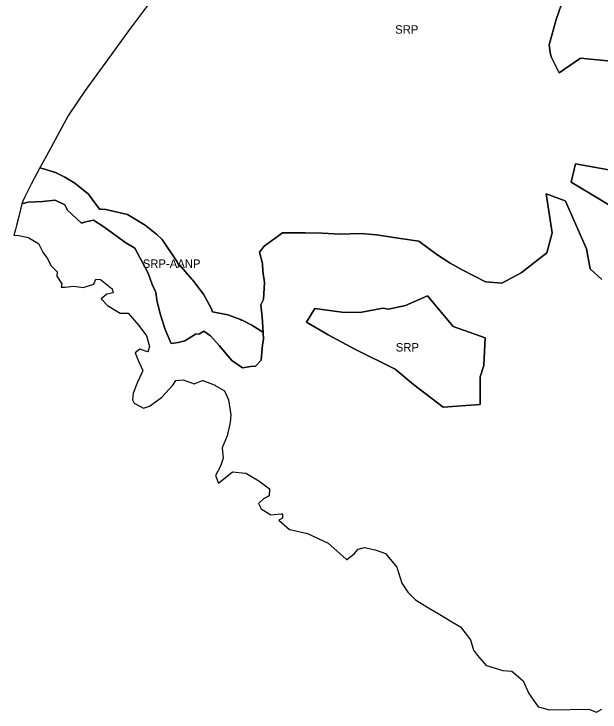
# Model space of a CAD drawing. Extents: x 598968 to 613553, y 4409678 to 4430833.
# Drawn here: x 598968 to 599801, y 4411640 to 4412632 of the extents above; entities that cross this region are included whole.
import ezdxf

# ---------------------------------------------------------------- set-up
doc = ezdxf.new("R2010")
doc.units = 0
doc.layers.add('Sòl Rústic Protegit', color=7, linetype='Continuous')
doc.layers.add('Sòl Rústic Protegit - Alt Nivell de Protecció', color=7, linetype='Continuous')

msp = doc.modelspace()

# ---------------------------------------------------------------- linework, layer by layer
at = {"layer": 'Sòl Rústic Protegit'}
for points in [[(599167.4801, 4412657.9802), (599130.5701, 4412607.8402), (599101.9801, 4412568.9202), (599068.9101, 4412523.2802), (599045.2201, 4412487.9502), (599014.1301, 4412430.5402), (599004.6743, 4412413.1288), (599009.8671, 4412412.0102), (599027.0547, 4412406.5102), (599040.1797, 4412400.0102), (599054.3671, 4412391.5102), (599073.6797, 4412376.0102), (599089.2423, 4412354.5102), (599091.6171, 4412354.5102), (599098.3671, 4412354.0102), (599129.2423, 4412347.0102), (599154.3047, 4412332.0102), (599170.8047, 4412318.5102), (599178.1797, 4412311.5102), (599199.8671, 4412279.5102), (599200.4923, 4412277.5102), (599200.9297, 4412277.0102), (599202.9297, 4412274.0102), (599205.3671, 4412272.5102), (599220.7421, 4412255.0102), (599221.8047, 4412253.5102), (599226.4297, 4412248.0102), (599236.9923, 4412233.5102), (599248.5547, 4412213.0102), (599250.1173, 4412208.5102), (599271.8047, 4412204.5102), (599289.9297, 4412197.5102), (599290.9297, 4412196.5102), (599292.1797, 4412196.5102), (599305.6173, 4412189.5102), (599318.8671, 4412181.5102), (599321.9925, 4412179.01), (599320.6801, 4412201.5098), (599318.8051, 4412218.5098), (599322.3677, 4412226.0098), (599323.9927, 4412250.5098), (599321.4927, 4412266.5098), (599321.0551, 4412277.5098), (599316.6177, 4412293.5098), (599323.3677, 4412302.0098), (599349.4927, 4412321.0098), (599381.4301, 4412321.0098), (599405.7427, 4412320.5098), (599431.4301, 4412319.0098), (599445.4301, 4412319.5098), (599460.7427, 4412320.0098), (599483.1801, 4412318.0098), (599517.3051, 4412313.0098), (599542.9927, 4412309.0098), (599568.6177, 4412290.0098), (599587.6177, 4412278.0098), (599604.6177, 4412268.5098), (599637.8677, 4412251.0098), (599660.9301, 4412249.5098), (599688.5551, 4412264.0098), (599725.1801, 4412292.5098), (599732.4301, 4412321.0098), (599723.9301, 4412376.5098), (599751.1801, 4412366.5098), (599751.3801, 4412366.0538), (599781.2427, 4412298.0098), (599786.7427, 4412269.5098), (599803.3051, 4412254.5098)], [(599815.9927, 4412565.0098), (599772.8879, 4412569.1888), (599742.8283, 4412548.3784), (599731.3677, 4412571.0098), (599729.8677, 4412577.5098), (599728.1801, 4412588.0098), (599738.3677, 4412624.0098), (599749.3051, 4412656.0098)], [(599848.5769, 4412339.5676), (599759.4317, 4412392.7276), (599765.9745, 4412418.8986), (599828.9485, 4412407.4488)]]:
    msp.add_lwpolyline(points, dxfattribs=at)
msp.add_lwpolyline([(599555.4927, 4412231.5098), (599524.0551, 4412217.5098), (599499.9301, 4412212.5098), (599492.2427, 4412214.0098), (599459.8677, 4412207.5098), (599433.6177, 4412208.0098), (599395.2163, 4412213.0984), (599383.6549, 4412193.8296), (599414.4855, 4412176.102), (599452.2525, 4412155.2916), (599509.4927, 4412127.0098), (599535.4943, 4412105.1922), (599577.8861, 4412072.8204), (599630.2975, 4412076.6742), (599630.2975, 4412115.983), (599635.6929, 4412132.1688), (599637.2345, 4412171.4776), (599591.7597, 4412187.6634)], close=True, dxfattribs=at)
at = {"layer": 'Sòl Rústic Protegit - Alt Nivell de Protecció'}
for points in [[(599749.3051, 4412656.0098), (599738.3677, 4412624.0098), (599728.1801, 4412588.0098), (599729.8677, 4412577.5098), (599731.3677, 4412571.0098), (599742.8283, 4412548.3784), (599772.8879, 4412569.1888), (599815.9927, 4412565.0098)], [(599828.9485, 4412407.4488), (599765.9745, 4412418.8986), (599759.4317, 4412392.7276), (599848.5769, 4412339.5676)], [(599803.3051, 4412254.5098), (599786.7427, 4412269.5098), (599781.2427, 4412298.0098), (599751.3801, 4412366.0538), (599751.1801, 4412366.5098), (599723.9301, 4412376.5098), (599732.4301, 4412321.0098), (599725.1801, 4412292.5098), (599688.5551, 4412264.0098), (599660.9301, 4412249.5098), (599637.8677, 4412251.0098), (599604.6177, 4412268.5098), (599587.6177, 4412278.0098), (599568.6177, 4412290.0098), (599542.9927, 4412309.0098), (599517.3051, 4412313.0098), (599483.1801, 4412318.0098), (599460.7427, 4412320.0098), (599445.4301, 4412319.5098), (599431.4301, 4412319.0098), (599405.7427, 4412320.5098), (599381.4301, 4412321.0098), (599349.4927, 4412321.0098), (599323.3677, 4412302.0098), (599316.6177, 4412293.5098), (599321.0551, 4412277.5098), (599321.4927, 4412266.5098), (599323.9927, 4412250.5098), (599322.3677, 4412226.0098), (599318.8051, 4412218.5098), (599320.6801, 4412201.5098), (599321.9925, 4412179.01), (599322.5549, 4412169.51), (599320.9299, 4412161.51), (599319.1799, 4412140.01), (599311.1799, 4412131.51), (599304.1799, 4412131.01), (599292.7425, 4412129.01), (599277.6175, 4412139.51), (599259.6175, 4412160.51), (599246.9299, 4412174.51), (599237.7425, 4412181.01), (599231.4925, 4412177.51), (599225.7425, 4412177.01), (599216.9925, 4412171.01), (599210.7425, 4412167.51), (599201.2425, 4412165.01), (599191.0549, 4412163.51), (599182.6799, 4412183.51), (599175.4299, 4412205.51), (599170.8675, 4412225.01), (599169.1799, 4412236.51), (599168.3553, 4412238.3708), (599164.3049, 4412247.51), (599160.7425, 4412257.01), (599157.9299, 4412264.51), (599139.3675, 4412299.01), (599126.9299, 4412306.51), (599107.8675, 4412320.51), (599095.3675, 4412329.51), (599080.9925, 4412339.01), (599069.5549, 4412336.51), (599063.8675, 4412334.51), (599043.9925, 4412353.01), (599039.8675, 4412360.51), (599026.1799, 4412367.51), (599008.9925, 4412365.51), (598987.9925, 4412364.51), (598979.1175, 4412362.01), (598974.6154, 4412344.0764), (598971.3708, 4412331.1519), (598969.9525, 4412325.5023), (598967.7959, 4412316.9118), (598972.3403, 4412317.6168), (598988.5903, 4412314.1168), (598988.7487, 4412314.022), (599002.7777, 4412305.617), (599008.5903, 4412293.6172), (599016.1527, 4412283.6172), (599020.0277, 4412274.6174), (599028.9651, 4412265.6176), (599028.6527, 4412259.1176), (599035.7151, 4412248.6178), (599035.0275, 4412243.6178), (599035.2561, 4412243.6178), (599040.6525, 4412243.6178), (599052.9027, 4412245.1178), (599066.3401, 4412243.118), (599081.3401, 4412248.118), (599084.0277, 4412255.118), (599090.7777, 4412254.618), (599090.9017, 4412254.5166), (599107.2777, 4412241.1184), (599108.8401, 4412235.6184), (599099.8401, 4412233.6184), (599091.6527, 4412227.1182), (599100.5901, 4412217.6184), (599118.7777, 4412206.6186), (599118.8127, 4412206.6186), (599130.0277, 4412206.6188), (599130.1235, 4412206.5098), (599145.4025, 4412189.119), (599155.9651, 4412174.6192), (599160.5275, 4412159.1194), (599158.4151, 4412153.3584), (599157.7775, 4412151.6194), (599156.2977, 4412152.1486), (599149.3641, 4412154.6274), (599147.3355, 4412155.3526), (599146.5899, 4412155.6192), (599140.0899, 4412150.1192), (599144.5899, 4412138.6194), (599150.3277, 4412126.226), (599150.8399, 4412125.1194), (599149.8729, 4412122.9922), (599143.3397, 4412108.6196), (599137.2771, 4412093.1196), (599136.2771, 4412083.6196), (599138.7771, 4412078.6198), (599151.9021, 4412071.6198), (599151.9077, 4412071.6218), (599160.4021, 4412074.62), (599177.4023, 4412086.62), (599193.5273, 4412104.12), (599198.0273, 4412111.12), (599208.1525, 4412112.12), (599223.7149, 4412106.1202), (599235.5899, 4412111.1202), (599236.3215, 4412110.8378), (599252.3571, 4412104.6448), (599253.7149, 4412104.1204), (599253.8335, 4412104.0488), (599266.9649, 4412096.1206), (599272.7149, 4412083.6208), (599275.9023, 4412062.121), (599275.1523, 4412051.121), (599270.8397, 4412032.121), (599263.5897, 4412015.1212), (599265.2771, 4412000.6212), (599261.3395, 4411989.1214), (599254.3395, 4411976.1214), (599258.2769, 4411965.1214), (599258.4135, 4411965.2306), (599278.2771, 4411981.1216), (599296.9645, 4411979.1216), (599297.1481, 4411979.0132), (599315.5895, 4411968.1218), (599331.0271, 4411957.122), (599330.5895, 4411947.1222), (599322.2145, 4411942.6222), (599315.2145, 4411936.1222), (599319.1519, 4411928.6222), (599332.6519, 4411920.1224), (599332.6841, 4411920.1254), (599337.4215, 4411920.5496), (599347.4619, 4411921.4488), (599349.4019, 4411921.6224), (599349.4441, 4411920.163), (599349.5895, 4411915.1226), (599344.3393, 4411912.6226), (599359.5269, 4411899.1228), (599359.6441, 4411899.0974), (599384.7769, 4411893.623), (599414.3395, 4411879.6234), (599414.3669, 4411879.599), (599435.1519, 4411861.1236), (599440.5893, 4411856.6236), (599440.6305, 4411856.6544), (599451.2769, 4411864.6236), (599457.1519, 4411871.1236), (599465.8395, 4411873.6238), (599481.2769, 4411870.1238), (599495.9019, 4411865.124), (599495.9483, 4411865.0676), (599511.9645, 4411845.6244), (599519.0893, 4411822.6246), (599527.7769, 4411810.1246), (599538.5893, 4411799.1248), (599554.5267, 4411789.125), (599573.0267, 4411778.1252), (599590.9643, 4411767.6254), (599602.5267, 4411760.6256), (599616.4017, 4411742.1258), (599620.6517, 4411727.626), (599626.5267, 4411720.1262), (599639.0267, 4411705.6264), (599639.1821, 4411705.58), (599662.4017, 4411698.6266), (599675.0267, 4411697.6266), (599675.1623, 4411697.5162), (599691.5891, 4411684.1268), (599699.4015, 4411666.127), (599712.7765, 4411647.1274), (599712.9429, 4411647.0804), (599728.7139, 4411642.6276), (599757.9635, 4411643.1278), (599784.7133, 4411643.6282), (599795.5255, 4411639.6282), (599803.4631, 4411643.6284)]]:
    msp.add_lwpolyline(points, dxfattribs=at)
for points in [[(599321.9925, 4412179.01), (599318.8671, 4412181.5102), (599305.6173, 4412189.5102), (599292.1797, 4412196.5102), (599290.9297, 4412196.5102), (599289.9297, 4412197.5102), (599271.8047, 4412204.5102), (599250.1173, 4412208.5102), (599248.5547, 4412213.0102), (599236.9923, 4412233.5102), (599226.4297, 4412248.0102), (599221.8047, 4412253.5102), (599220.7421, 4412255.0102), (599205.3671, 4412272.5102), (599202.9297, 4412274.0102), (599200.9297, 4412277.0102), (599200.4923, 4412277.5102), (599199.8671, 4412279.5102), (599178.1797, 4412311.5102), (599170.8047, 4412318.5102), (599154.3047, 4412332.0102), (599129.2423, 4412347.0102), (599098.3671, 4412354.0102), (599091.6171, 4412354.5102), (599089.2423, 4412354.5102), (599073.6797, 4412376.0102), (599054.3671, 4412391.5102), (599040.1797, 4412400.0102), (599027.0547, 4412406.5102), (599009.8671, 4412412.0102), (599004.6743, 4412413.1288), (598992.0701, 4412389.9202), (598982.9601, 4412371.0002), (598980.2278, 4412365.7925), (598979.1175, 4412362.01), (598987.9925, 4412364.51), (599008.9925, 4412365.51), (599026.1799, 4412367.51), (599039.8675, 4412360.51), (599043.9925, 4412353.01), (599063.8675, 4412334.51), (599069.5549, 4412336.51), (599080.9925, 4412339.01), (599095.3675, 4412329.51), (599107.8675, 4412320.51), (599126.9299, 4412306.51), (599139.3675, 4412299.01), (599157.9299, 4412264.51), (599160.7425, 4412257.01), (599164.3049, 4412247.51), (599168.3553, 4412238.3708), (599169.1799, 4412236.51), (599170.8675, 4412225.01), (599175.4299, 4412205.51), (599182.6799, 4412183.51), (599191.0549, 4412163.51), (599201.2425, 4412165.01), (599210.7425, 4412167.51), (599216.9925, 4412171.01), (599225.7425, 4412177.01), (599231.4925, 4412177.51), (599237.7425, 4412181.01), (599246.9299, 4412174.51), (599259.6175, 4412160.51), (599277.6175, 4412139.51), (599292.7425, 4412129.01), (599304.1799, 4412131.01), (599311.1799, 4412131.51), (599319.1799, 4412140.01), (599320.9299, 4412161.51), (599322.5549, 4412169.51)], [(599555.4927, 4412231.5098), (599591.7597, 4412187.6634), (599637.2345, 4412171.4776), (599635.6929, 4412132.1688), (599630.2975, 4412115.983), (599630.2975, 4412076.6742), (599577.8861, 4412072.8204), (599535.4943, 4412105.1922), (599509.4927, 4412127.0098), (599452.2525, 4412155.2916), (599414.4855, 4412176.102), (599383.6549, 4412193.8296), (599395.2163, 4412213.0984), (599433.6177, 4412208.0098), (599459.8677, 4412207.5098), (599492.2427, 4412214.0098), (599499.9301, 4412212.5098), (599524.0551, 4412217.5098)]]:
    msp.add_lwpolyline(points, close=True, dxfattribs=at)

# ---------------------------------------------------------------- texts
at = {"layer": 'Sòl Rústic Protegit'}
for p in [(599509.4895, 4412604.0438), (599510.4447, 4412152.1651)]:
    msp.add_text('SRP', height=12, dxfattribs=at).set_placement(p)
at = {"layer": 'Sòl Rústic Protegit - Alt Nivell de Protecció'}
msp.add_text('SRP-AANP', height=12, dxfattribs=at).set_placement((599150.8362, 4412271.0694))

doc.saveas('drawing.dxf')
